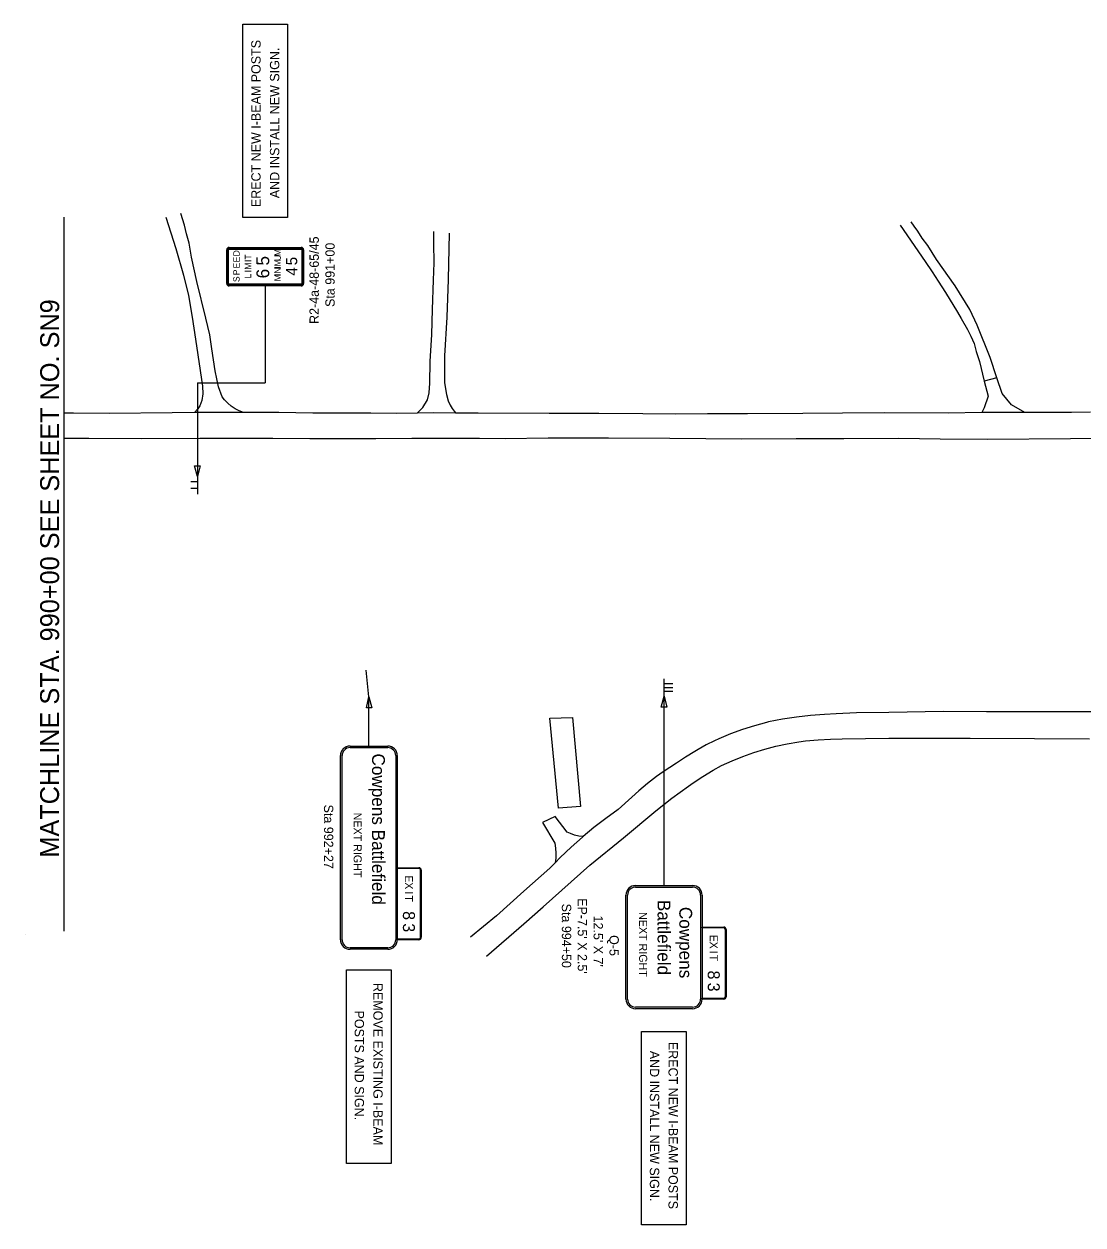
# Model space of a CAD drawing. Extents: x 1738744 to 1740332, y 1166701 to 1167640.
# Drawn here: x 1738744 to 1739538, y 1166701 to 1167602 of the extents above; entities that cross this region are included whole.
import ezdxf

# ---------------------------------------------------------------- set-up
doc = ezdxf.new("R2010")
doc.units = 0
for name, color, linetype in [('Default', 7, 'Continuous'), ('RD_EX_Bldg', 7, 'Continuous'), ('RD_EX_Driveway', 7, 'Continuous'), ('RD_EX_Road', 7, 'Continuous'), ('RD_SHT_MatchLine', 7, 'Continuous'), ('RD_SHT_TX', 7, 'Continuous'), ('SN_P_Signs', 7, 'Continuous')]:
    doc.layers.add(name, color=color, linetype=linetype)

msp = doc.modelspace()

# ---------------------------------------------------------------- linework, layer by layer
at = {"layer": 'RD_EX_Bldg'}
msp.add_lwpolyline([(1739144.5, 1167013.94), (1739138.16, 1167081.39), (1739155.01, 1167082.07), (1739161.1, 1167015.17), (1739144.5, 1167013.94)], dxfattribs=at)
at = {"layer": 'RD_EX_Driveway'}
for points in [[(1738908.4, 1167310.67), (1738908.24, 1167310.73), (1738905.14, 1167311.88), (1738902.04, 1167313.45), (1738899.14, 1167315.37), (1738896.48, 1167317.6), (1738894.08, 1167320.12), (1738892.39, 1167322.3), (1738889.68, 1167329.93), (1738887.19, 1167341.79), (1738884.6, 1167358.27), (1738883.07, 1167368.85), (1738880.15, 1167381.43), (1738873.3, 1167408.83), (1738869.43, 1167427.05), (1738867.52, 1167437.53), (1738865.55, 1167444.62), (1738864.09, 1167451.05), (1738861.36, 1167459.86)], [(1738850.06, 1167457.05), (1738857.64, 1167433.5), (1738863.45, 1167413.54), (1738866.98, 1167398.46), (1738869.84, 1167382.22), (1738872.38, 1167365.69), (1738877.5, 1167330.31), (1738877.91, 1167324.63), (1738877.15, 1167319.69), (1738875.56, 1167315.74), (1738874.09, 1167313.48), (1738871.51, 1167310.57)], [(1739400.69, 1167451.08), (1739419.51, 1167423.91), (1739424.82, 1167416.21), (1739429.37, 1167409.04), (1739434.8, 1167400.57), (1739443.77, 1167385.83), (1739446.55, 1167381.21), (1739451.22, 1167372.75), (1739453.87, 1167367.75), (1739456.27, 1167362.36), (1739457.89, 1167356.47), (1739460.39, 1167348.91), (1739463.88, 1167334.06)], [(1739473.3, 1167336.59), (1739468.42, 1167351.97), (1739458.49, 1167376.19), (1739453.08, 1167387.97), (1739441.96, 1167405.53), (1739428.06, 1167425.27), (1739421.5, 1167435.9), (1739417.33, 1167441.41), (1739414.17, 1167446.53), (1739411.39, 1167450.37), (1739409.12, 1167453.58)], [(1739038.5, 1167310.19), (1739042.93, 1167314.5), (1739046.24, 1167320.04), (1739047.6, 1167325.49), (1739048.01, 1167332.72), (1739048.36, 1167349), (1739049.5, 1167369.02), (1739050.09, 1167387.9), (1739050.94, 1167409.91), (1739051.35, 1167422.83), (1739051.01, 1167437.31), (1739051.07, 1167446.46)], [(1739062.52, 1167444.99), (1739061.92, 1167410.38), (1739060.87, 1167382.15), (1739059.08, 1167353.12), (1739059.05, 1167332.86), (1739060.49, 1167324.22), (1739061.77, 1167319.49), (1739063.39, 1167316.13), (1739064.84, 1167313.68), (1739066.3, 1167311.56), (1739067.54, 1167310.21)], [(1739494.25, 1167310.61), (1739484.27, 1167316.36), (1739477.37, 1167324.85), (1739473.3, 1167336.59), (1739463.88, 1167334.06), (1739466.79, 1167322.83), (1739463.85, 1167314.12), (1739462.03, 1167310.62)], [(1739162.99, 1166992.69), (1739159.92, 1166993.01), (1739156.63, 1166993.75), (1739153.45, 1166994.87), (1739151.08, 1166995.99), (1739142, 1167007.62), (1739132.47, 1167003.31), (1739141.73, 1166987.64), (1739142.37, 1166983.96), (1739142.63, 1166980.22), (1739142.49, 1166976.48), (1739142.01, 1166973.01)]]:
    msp.add_lwpolyline(points, dxfattribs=at)
at = {"layer": 'RD_EX_Road'}
for points in [[(1739543.45, 1167310.78), (1739529.2, 1167310.56), (1739494.25, 1167310.61), (1739485.91, 1167310.63), (1739468.19, 1167310.74), (1739462.03, 1167310.62), (1739436.8, 1167310.1), (1739389.07, 1167310.27), (1739357.49, 1167310.08), (1739327.71, 1167309.87), (1739286.43, 1167309.61), (1739256.28, 1167309.73), (1739232.31, 1167309.49), (1739207.79, 1167309.64), (1739174.82, 1167309.78), (1739137.47, 1167309.82), (1739084.41, 1167310.05), (1739067.54, 1167310.21), (1739051.18, 1167310.37), (1739038.5, 1167310.19), (1739023.42, 1167309.99), (1739003.83, 1167310.15), (1738983.91, 1167310.25), (1738960.39, 1167310.17), (1738934.93, 1167310.58), (1738915.27, 1167310.75), (1738908.24, 1167310.73), (1738877.54, 1167310.64), (1738871.51, 1167310.57), (1738854.78, 1167310.38), (1738807.59, 1167310), (1738780.75, 1167310.19), (1738773.73, 1167310.22)], [(1739554.34, 1167291.23), (1739528.65, 1167290.91), (1739466.27, 1167290.46), (1739430.87, 1167290.67), (1739399.73, 1167291.25), (1739358.53, 1167290.99), (1739322.93, 1167290.95), (1739282.19, 1167290.75), (1739228.09, 1167291.08), (1739182.16, 1167291.3), (1739136.88, 1167291.32), (1739104.57, 1167290.89), (1739085.45, 1167291.11), (1739065.86, 1167291.14), (1739034.57, 1167291.09), (1739007.51, 1167290.96), (1738983.14, 1167291.02), (1738957.98, 1167290.98), (1738930.41, 1167291.05), (1738875.69, 1167291.05), (1738832.08, 1167290.9), (1738792.23, 1167291.19), (1738773.73, 1167291.19)], [(1739549.43, 1167086.09), (1739465.49, 1167086.14), (1739433.32, 1167086.34), (1739392.41, 1167085.67), (1739368.08, 1167085.45), (1739352.92, 1167084.8), (1739344.06, 1167084.24), (1739333.5, 1167083.42), (1739322.98, 1167082.21), (1739312.51, 1167080.6), (1739302.11, 1167078.61), (1739300.65, 1167078.3), (1739291.51, 1167075.8), (1739282.48, 1167072.92), (1739273.57, 1167069.67), (1739264.81, 1167066.06), (1739261.45, 1167064.55), (1739255.25, 1167061.45), (1739249.23, 1167058), (1739246.82, 1167056.48), (1739239.92, 1167052.15), (1739233.02, 1167047.82), (1739223.07, 1167041.18), (1739218.17, 1167037.73), (1739211.32, 1167032.5), (1739204.72, 1167026.97), (1739199.57, 1167022.27), (1739189.25, 1167012.93), (1739180.09, 1167006.35), (1739171.16, 1166999.46), (1739162.99, 1166992.69), (1739162.47, 1166992.26), (1739154.04, 1166984.76), (1739145.88, 1166976.98), (1739142.01, 1166973.01), (1739138.09, 1166969), (1739118.66, 1166951.63), (1739098.06, 1166933.23), (1739078.69, 1166917.2)], [(1739090.65, 1166902.96), (1739118.47, 1166927.34), (1739133.01, 1166940.09), (1739168.08, 1166971.16), (1739193.26, 1166991.75), (1739217.53, 1167012.09), (1739229.65, 1167021.45), (1739241.99, 1167030.5), (1739245.45, 1167032.94), (1739252.84, 1167037.82), (1739260.45, 1167042.36), (1739266.88, 1167045.85), (1739274.75, 1167049.52), (1739282.78, 1167052.83), (1739290.96, 1167055.77), (1739299.25, 1167058.33), (1739307.66, 1167060.52), (1739316.16, 1167062.32), (1739324.73, 1167063.73), (1739329.81, 1167064.38), (1739339.2, 1167065.28), (1739348.63, 1167065.78), (1739357.22, 1167065.9), (1739392.27, 1167066.52), (1739453.21, 1167066.5), (1739501.43, 1167066.1), (1739542.74, 1167066.04)]]:
    msp.add_lwpolyline(points, dxfattribs=at)
at = {"layer": 'RD_SHT_MatchLine'}
msp.add_lwpolyline([(1738773.73, 1166921.86), (1738773.73, 1167194.04), (1738773.73, 1167456.99)], dxfattribs=at)
at = {"layer": 'SN_P_Signs'}
for p, q in [((1738907.8, 1167456.89), (1738907.8, 1167601.91)), ((1738907.8, 1167601.91), (1738941.42, 1167601.91)), ((1738941.42, 1167601.91), (1738941.42, 1167456.89)), ((1738941.42, 1167456.89), (1738907.8, 1167456.89)), ((1738895.81, 1167407.38), (1738895.81, 1167432.58)), ((1738897.61, 1167434.38), (1738951.61, 1167434.38)), ((1738953.41, 1167432.58), (1738953.41, 1167407.38)), ((1738951.61, 1167405.58), (1738897.61, 1167405.58)), ((1738924.61, 1167405.58), (1738924.61, 1167332.88)), ((1738873.73, 1167332.88), (1738873.73, 1167262.56)), ((1738873.73, 1167332.88), (1738924.61, 1167332.88)), ((1738873.73, 1167262.56), (1738873.73, 1167249.52)), ((1738873.73, 1167258.65), (1738868.74, 1167258.65)), ((1738873.73, 1167253.63), (1738868.74, 1167253.63)), ((1739002.37, 1167097.44), (1739000.23, 1167117.48)), ((1739223.73, 1167098.02), (1739223.73, 1167111.06)), ((1739223.73, 1167107.48), (1739230.25, 1167107.48)), ((1739002.37, 1167060.55), (1739002.37, 1167097.44)), ((1739223.73, 1167104.54), (1739230.25, 1167104.54)), ((1739223.73, 1167101.61), (1739230.25, 1167101.61)), ((1739223.73, 1166956), (1739223.73, 1167098.02)), ((1738985.47, 1166747.66), (1738985.47, 1166892.68)), ((1738985.47, 1166892.68), (1739019.08, 1166892.68)), ((1739019.08, 1166892.68), (1739019.08, 1166747.66)), ((1739206.83, 1166701.47), (1739206.83, 1166846.49)), ((1739206.83, 1166846.49), (1739240.44, 1166846.49)), ((1739240.44, 1166846.49), (1739240.44, 1166701.47)), ((1739019.08, 1166747.66), (1738985.47, 1166747.66)), ((1739240.44, 1166701.47), (1739206.83, 1166701.47))]:
    msp.add_line(p, q, dxfattribs=at)
for points in [[(1738896.26, 1167407.38), (1738896.26, 1167432.58)], [(1738897.01, 1167407.38), (1738897.01, 1167432.58)], [(1738897.61, 1167433.93), (1738951.61, 1167433.93)], [(1738897.61, 1167433.18), (1738951.61, 1167433.18)], [(1738952.21, 1167432.58), (1738952.21, 1167407.38)], [(1738952.96, 1167432.58), (1738952.96, 1167407.38)], [(1738951.61, 1167406.78), (1738897.61, 1167406.78)], [(1738951.61, 1167406.03), (1738897.61, 1167406.03)], [(1738981.05, 1166915.35), (1738981.05, 1167053.35)], [(1738982.25, 1166915.35), (1738982.25, 1167053.35)], [(1738988.25, 1167060.55), (1739016.49, 1167060.55)], [(1738988.25, 1167059.35), (1739016.49, 1167059.35)], [(1739022.49, 1167053.35), (1739022.49, 1166915.35)], [(1739023.69, 1167053.35), (1739023.69, 1166915.35)], [(1739039.89, 1166968.75), (1739023.69, 1166968.75), (1739023.69, 1166969.35), (1739039.89, 1166969.35)], [(1739041.09, 1166917.15), (1739041.09, 1166967.55)], [(1739041.69, 1166967.55), (1739041.69, 1166917.15)], [(1739202.36, 1166956), (1739245.11, 1166956)], [(1739202.36, 1166954.8), (1739245.11, 1166954.8)], [(1739195.16, 1166870.8), (1739195.16, 1166948.8)], [(1739196.36, 1166870.8), (1739196.36, 1166948.8)], [(1739251.11, 1166948.8), (1739251.11, 1166870.8)], [(1739252.31, 1166948.8), (1739252.31, 1166870.8)], [(1739268.51, 1166924.2), (1739252.31, 1166924.2), (1739252.31, 1166924.8), (1739268.51, 1166924.8)], [(1739269.71, 1166872.6), (1739269.71, 1166923)], [(1739270.31, 1166923), (1739270.31, 1166872.6)], [(1739016.49, 1166909.35), (1738988.25, 1166909.35)], [(1739039.89, 1166915.35), (1739023.69, 1166915.35), (1739023.69, 1166915.95)], [(1739023.69, 1166915.95), (1739039.89, 1166915.95)], [(1739016.49, 1166908.15), (1738988.25, 1166908.15)], [(1739245.11, 1166864.8), (1739202.36, 1166864.8)], [(1739245.11, 1166863.6), (1739202.36, 1166863.6)], [(1739268.51, 1166870.8), (1739252.31, 1166870.8), (1739252.31, 1166871.4)], [(1739252.31, 1166871.4), (1739268.51, 1166871.4)]]:
    msp.add_lwpolyline(points, dxfattribs=at)
for points in [[(1738875.79, 1167270.76), (1738873.73, 1167262.56), (1738871.68, 1167270.76)], [(1739000.46, 1167089.21), (1739002.42, 1167097.44), (1739004.56, 1167089.26)], [(1739221.68, 1167089.82), (1739223.73, 1167098.02), (1739225.79, 1167089.82)]]:
    msp.add_lwpolyline(points, close=True, dxfattribs=at)
for centre, radius, start, end in [((1738897.61, 1167432.58), 1.8, 90, 180), ((1738897.61, 1167432.58), 1.35, 90, 180), ((1738897.61, 1167432.58), 0.6, 90, 180), ((1738951.61, 1167432.58), 1.8, 0, 90), ((1738951.61, 1167432.58), 1.35, 0, 90), ((1738951.61, 1167432.58), 0.6, 0, 90), ((1738897.61, 1167407.38), 1.8, 180, 270), ((1738897.61, 1167407.38), 1.35, 180, 270), ((1738897.61, 1167407.38), 0.6, 180, 270), ((1738951.61, 1167407.38), 0.6, 270, 0), ((1738951.61, 1167407.38), 1.35, 270, 0), ((1738951.61, 1167407.38), 1.8, 270, 0), ((1738988.25, 1167053.35), 7.2, 90, 180), ((1738988.25, 1167053.35), 6, 90, 180), ((1739016.49, 1167053.35), 7.2, 0, 90), ((1739016.49, 1167053.35), 6, 0, 90), ((1739039.89, 1166967.55), 1.8, 0, 90), ((1739039.89, 1166967.55), 1.2, 0, 90), ((1739202.36, 1166948.8), 7.2, 90, 180), ((1739202.36, 1166948.8), 6, 90, 180), ((1739245.11, 1166948.8), 7.2, 0, 90), ((1739245.11, 1166948.8), 6, 0, 90), ((1739268.51, 1166923), 1.8, 0, 90), ((1739268.51, 1166923), 1.2, 0, 90), ((1738988.25, 1166915.35), 7.2, 180, 270), ((1738988.25, 1166915.35), 6, 180, 270), ((1739016.49, 1166915.35), 6, 270, 360), ((1739016.49, 1166915.35), 7.2, 270, 0), ((1739039.89, 1166917.15), 1.8, 270, 0), ((1739039.89, 1166917.15), 1.2, 270, 0), ((1739268.51, 1166872.6), 1.8, 270, 0), ((1739268.51, 1166872.6), 1.2, 270, 0), ((1739202.36, 1166870.8), 7.2, 180, 270), ((1739202.36, 1166870.8), 6, 180, 270), ((1739245.11, 1166870.8), 6, 270, 360), ((1739245.11, 1166870.8), 7.2, 270, 0)]:
    msp.add_arc(centre, radius, start, end, dxfattribs=at)

# ---------------------------------------------------------------- texts
at = {"layer": 'Default'}
for s, height, p in [('Angle:  25.9453', 0.2083, (1738743.73, 1166918.56)), ('Align: A_I85', 0.2083, (1738743.73, 1166918.29)), ('Sheet: 10', 0.208, (1738743.73, 1166918.83))]:
    msp.add_text(s, height=height, dxfattribs=at).set_placement(p)
at = {"layer": 'RD_SHT_TX'}
msp.add_text('MATCHLINE STA. 990+00 SEE SHEET NO. SN9', height=14.1726, rotation=89.98556, dxfattribs=at).set_placement((1738769.97, 1166976.88))
at = {"layer": 'SN_P_Signs'}
for s, height, rotation, p in [('ERECT NEW I-BEAM POSTS', 6.9998, 90.00008, (1738921.17, 1167464.62)), ('AND INSTALL NEW SIGN.', 6.9998, 90.00008, (1738935.17, 1167471.32)), ('R2-4a-48-65/45', 7, 90.00008, (1738964.83, 1167377.05)), ('D', 4.8, 90, (1738905.41, 1167427.71)), ('M', 4.8, 90, (1738936.31, 1167427.87)), ('Sta 991+00', 7, 90.00008, (1738976.73, 1167389.78)), ('E', 4.8, 90, (1738905.41, 1167423.17)), ('E', 4.8, 90, (1738905.41, 1167418.63)), ('T', 4.8, 90, (1738914.11, 1167425.25)), ('I', 4.8, 90, (1738914.11, 1167423.43)), ('M', 4.8, 90, (1738914.11, 1167417.77)), ('5', 9.6, 90, (1738927.61, 1167420.82)), ('U', 4.8, 90, (1738936.31, 1167424.24)), ('M', 4.8, 90, (1738936.31, 1167420.11)), ('5', 8.4, 90, (1738948.61, 1167421.03)), ('S', 4.8, 90, (1738905.41, 1167408.43)), ('P', 4.8, 90, (1738905.41, 1167413.53)), ('I', 4.8, 90, (1738914.11, 1167415.71)), ('L', 4.8, 90, (1738914.11, 1167411.19)), ('6', 9.6, 90, (1738927.61, 1167411.19)), ('I', 4.8, 90, (1738936.31, 1167418.43)), ('N', 4.8, 90, (1738936.31, 1167414.79)), ('I', 4.8, 90, (1738936.31, 1167413.11)), ('M', 4.8, 90, (1738936.31, 1167408.98)), ('4', 8.4, 90, (1738948.61, 1167413.29)), ('Cowpens Battlefield', 9.6, 270, (1739004.75, 1167054.96)), ('Sta 992+27', 7, 270.00008, (1738968.68, 1167016.66)), ('NEXT RIGHT', 6, 270, (1738990.95, 1167010.63)), ('E', 6, 270, (1739029.39, 1166963.61)), ('X', 6, 270, (1739029.39, 1166958.46)), ('I', 6, 270, (1739029.39, 1166951.65)), ('T', 6, 270, (1739029.39, 1166948.67)), ("EP-7.5' X 2.5'", 7, 270.00008, (1739158.99, 1166946.46)), ('8', 9, 270, (1739027.89, 1166936.79)), ('Sta 994+50', 7, 270.00008, (1739147.09, 1166942.38)), ('NEXT RIGHT', 6, 270, (1739205.06, 1166936.09)), ('Battlefield', 9.6, 270, (1739218.86, 1166945.21)), ('Cowpens', 9.6, 270, (1739235.18, 1166939.96)), ('3', 9, 270, (1739027.89, 1166927.69)), ("12.5' X 7'", 7, 270.00008, (1739170.89, 1166933.45)), ('Q-5', 7, 270.00008, (1739182.79, 1166918.79)), ('E', 6, 270, (1739258.01, 1166919.07)), ('X', 6, 270, (1739258.01, 1166913.91)), ('I', 6, 270, (1739258.01, 1166907.1)), ('T', 6, 270, (1739258.01, 1166904.12)), ('8', 9, 270, (1739256.51, 1166892.24)), ('REMOVE EXISTING I-BEAM', 6.9998, 270.00008, (1739005.72, 1166882.93)), ('3', 9, 270, (1739256.51, 1166883.14)), ('POSTS AND SIGN.', 6.9998, 270.00008, (1738991.72, 1166862.23)), ('ERECT NEW I-BEAM POSTS', 6.9998, 270.00008, (1739227.08, 1166838.75)), ('AND INSTALL NEW SIGN.', 6.9998, 270.00008, (1739213.08, 1166832.06))]:
    msp.add_text(s, height=height, rotation=rotation, dxfattribs=at).set_placement(p)

doc.saveas('drawing.dxf')
